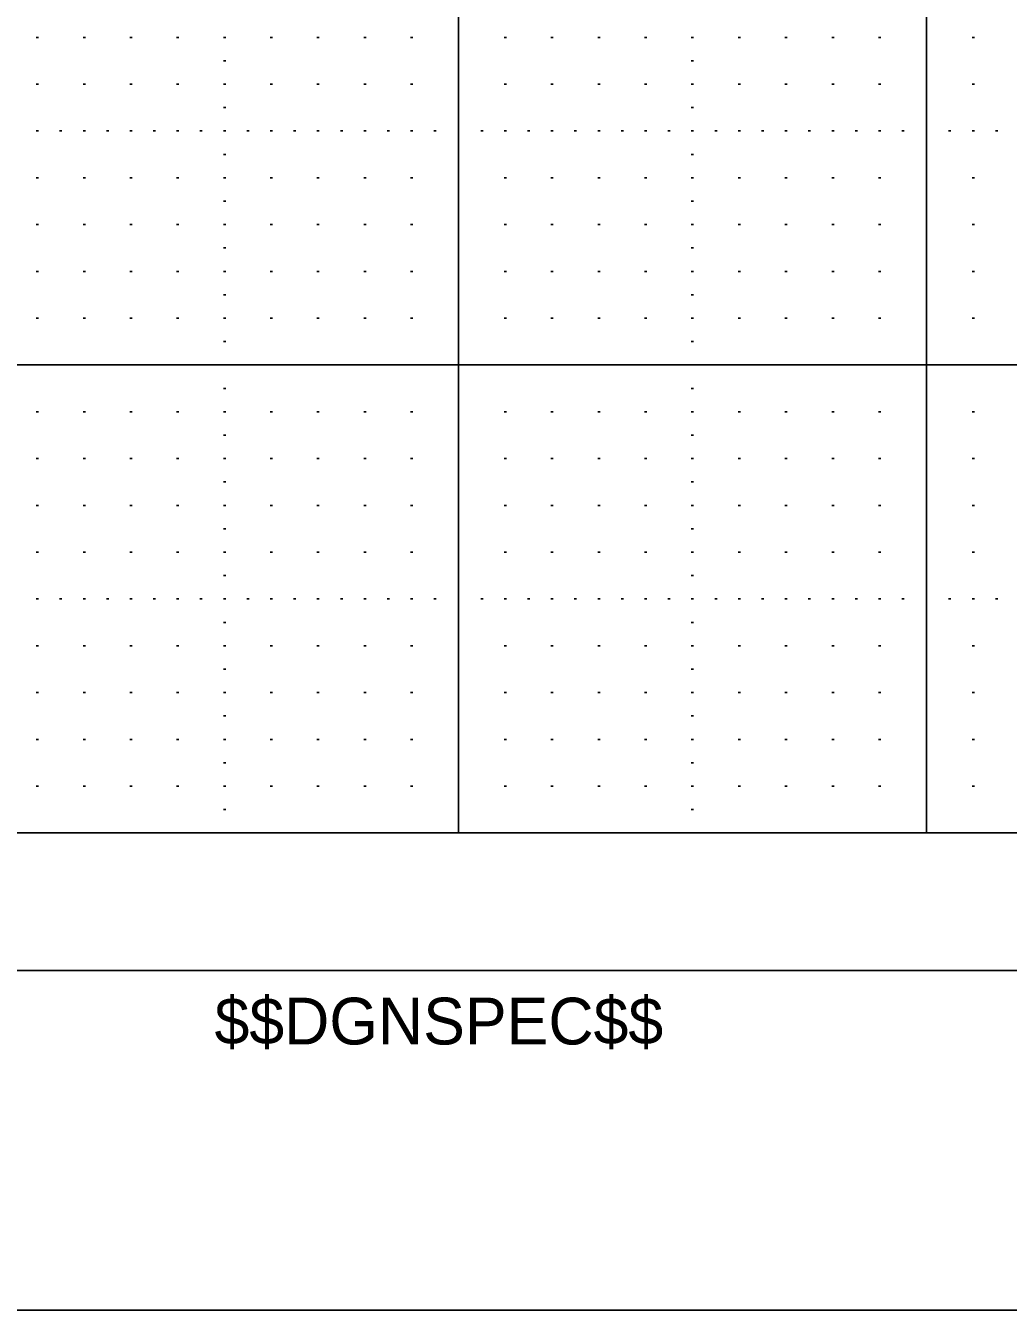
# Model space of a CAD drawing. Extents: x -1.6 to 32.4, y -0.7 to 21.3.
# Drawn here: x 21.82 to 23.92, y -0.727 to 2.018 of the extents above; entities that cross this region are included whole.
import ezdxf

# ---------------------------------------------------------------- set-up
doc = ezdxf.new("R2010")
doc.units = 0
for name, color, linetype in [('Level 1', 7, 'Continuous'), ('Level 4', 7, 'Continuous'), ('Level 48', 7, 'Continuous'), ('Level 5', 7, 'Continuous'), ('Level 63', 7, 'Continuous'), ('R_Border_Dark', 7, 'Continuous')]:
    doc.layers.add(name, color=color, linetype=linetype)

msp = doc.modelspace()

# ---------------------------------------------------------------- linework, layer by layer
at = {"layer": 'Level 1'}
msp.add_line((31.617, -0.001), (-0.001, -0.001), dxfattribs=at)
at = {"layer": 'Level 4'}
msp.add_line((31.617, 0.293), (-0.001, 0.293), dxfattribs=at)
at = {"layer": 'Level 5'}
for p, q in [((21.8425, 1.993), (21.8475, 1.993)), ((21.9425, 1.993), (21.9475, 1.993)), ((22.0425, 1.993), (22.0475, 1.993)), ((22.1425, 1.993), (22.1475, 1.993)), ((22.2425, 1.993), (22.2475, 1.993)), ((22.3425, 1.993), (22.3475, 1.993)), ((22.4425, 1.993), (22.4475, 1.993)), ((22.5425, 1.993), (22.5475, 1.993)), ((22.6425, 1.993), (22.6475, 1.993)), ((22.8425, 1.993), (22.8475, 1.993)), ((22.9425, 1.993), (22.9475, 1.993)), ((23.0425, 1.993), (23.0475, 1.993)), ((23.1425, 1.993), (23.1475, 1.993)), ((23.2425, 1.993), (23.2475, 1.993)), ((23.3425, 1.993), (23.3475, 1.993)), ((23.4425, 1.993), (23.4475, 1.993)), ((23.5425, 1.993), (23.5475, 1.993)), ((23.6425, 1.993), (23.6475, 1.993)), ((23.8425, 1.993), (23.8475, 1.993)), ((22.2425, 1.943), (22.2475, 1.943)), ((23.2425, 1.943), (23.2475, 1.943)), ((21.8425, 1.893), (21.8475, 1.893)), ((21.9425, 1.893), (21.9475, 1.893)), ((22.0425, 1.893), (22.0475, 1.893)), ((22.1425, 1.893), (22.1475, 1.893)), ((22.2425, 1.893), (22.2475, 1.893)), ((22.3425, 1.893), (22.3475, 1.893)), ((22.4425, 1.893), (22.4475, 1.893)), ((22.5425, 1.893), (22.5475, 1.893)), ((22.6425, 1.893), (22.6475, 1.893)), ((22.8425, 1.893), (22.8475, 1.893)), ((22.9425, 1.893), (22.9475, 1.893)), ((23.0425, 1.893), (23.0475, 1.893)), ((23.1425, 1.893), (23.1475, 1.893)), ((23.2425, 1.893), (23.2475, 1.893)), ((23.3425, 1.893), (23.3475, 1.893)), ((23.4425, 1.893), (23.4475, 1.893)), ((23.5425, 1.893), (23.5475, 1.893)), ((23.6425, 1.893), (23.6475, 1.893)), ((23.8425, 1.893), (23.8475, 1.893)), ((22.2425, 1.843), (22.2475, 1.843)), ((23.2425, 1.843), (23.2475, 1.843)), ((21.8425, 1.793), (21.8475, 1.793)), ((21.8925, 1.793), (21.8975, 1.793)), ((21.9425, 1.793), (21.9475, 1.793)), ((21.9925, 1.793), (21.9975, 1.793)), ((22.0425, 1.793), (22.0475, 1.793)), ((22.0925, 1.793), (22.0975, 1.793)), ((22.1425, 1.793), (22.1475, 1.793)), ((22.1925, 1.793), (22.1975, 1.793)), ((22.2425, 1.793), (22.2475, 1.793)), ((22.2925, 1.793), (22.2975, 1.793)), ((22.3425, 1.793), (22.3475, 1.793)), ((22.3925, 1.793), (22.3975, 1.793)), ((22.4425, 1.793), (22.4475, 1.793)), ((22.4925, 1.793), (22.4975, 1.793)), ((22.5425, 1.793), (22.5475, 1.793)), ((22.5925, 1.793), (22.5975, 1.793)), ((22.6425, 1.793), (22.6475, 1.793)), ((22.6925, 1.793), (22.6975, 1.793)), ((22.7925, 1.793), (22.7975, 1.793)), ((22.8425, 1.793), (22.8475, 1.793)), ((22.8925, 1.793), (22.8975, 1.793)), ((22.9425, 1.793), (22.9475, 1.793)), ((22.9925, 1.793), (22.9975, 1.793)), ((23.0425, 1.793), (23.0475, 1.793)), ((23.0925, 1.793), (23.0975, 1.793)), ((23.1425, 1.793), (23.1475, 1.793)), ((23.1925, 1.793), (23.1975, 1.793)), ((23.2425, 1.793), (23.2475, 1.793)), ((23.2925, 1.793), (23.2975, 1.793)), ((23.3425, 1.793), (23.3475, 1.793)), ((23.3925, 1.793), (23.3975, 1.793)), ((23.4425, 1.793), (23.4475, 1.793)), ((23.4925, 1.793), (23.4975, 1.793)), ((23.5425, 1.793), (23.5475, 1.793)), ((23.5925, 1.793), (23.5975, 1.793)), ((23.6425, 1.793), (23.6475, 1.793)), ((23.6925, 1.793), (23.6975, 1.793)), ((23.7925, 1.793), (23.7975, 1.793)), ((23.8425, 1.793), (23.8475, 1.793)), ((23.8925, 1.793), (23.8975, 1.793)), ((22.2425, 1.743), (22.2475, 1.743)), ((23.2425, 1.743), (23.2475, 1.743)), ((21.8425, 1.693), (21.8475, 1.693)), ((21.9425, 1.693), (21.9475, 1.693)), ((22.0425, 1.693), (22.0475, 1.693)), ((22.1425, 1.693), (22.1475, 1.693)), ((22.2425, 1.693), (22.2475, 1.693)), ((22.3425, 1.693), (22.3475, 1.693)), ((22.4425, 1.693), (22.4475, 1.693)), ((22.5425, 1.693), (22.5475, 1.693)), ((22.6425, 1.693), (22.6475, 1.693)), ((22.8425, 1.693), (22.8475, 1.693)), ((22.9425, 1.693), (22.9475, 1.693)), ((23.0425, 1.693), (23.0475, 1.693)), ((23.1425, 1.693), (23.1475, 1.693)), ((23.2425, 1.693), (23.2475, 1.693)), ((23.3425, 1.693), (23.3475, 1.693)), ((23.4425, 1.693), (23.4475, 1.693)), ((23.5425, 1.693), (23.5475, 1.693)), ((23.6425, 1.693), (23.6475, 1.693)), ((23.8425, 1.693), (23.8475, 1.693)), ((22.2425, 1.643), (22.2475, 1.643)), ((23.2425, 1.643), (23.2475, 1.643)), ((21.8425, 1.593), (21.8475, 1.593)), ((21.9425, 1.593), (21.9475, 1.593)), ((22.0425, 1.593), (22.0475, 1.593)), ((22.1425, 1.593), (22.1475, 1.593)), ((22.2425, 1.593), (22.2475, 1.593)), ((22.3425, 1.593), (22.3475, 1.593)), ((22.4425, 1.593), (22.4475, 1.593)), ((22.5425, 1.593), (22.5475, 1.593)), ((22.6425, 1.593), (22.6475, 1.593)), ((22.8425, 1.593), (22.8475, 1.593)), ((22.9425, 1.593), (22.9475, 1.593)), ((23.0425, 1.593), (23.0475, 1.593)), ((23.1425, 1.593), (23.1475, 1.593)), ((23.2425, 1.593), (23.2475, 1.593)), ((23.3425, 1.593), (23.3475, 1.593)), ((23.4425, 1.593), (23.4475, 1.593)), ((23.5425, 1.593), (23.5475, 1.593)), ((23.6425, 1.593), (23.6475, 1.593)), ((23.8425, 1.593), (23.8475, 1.593)), ((22.2425, 1.543), (22.2475, 1.543)), ((23.2425, 1.543), (23.2475, 1.543)), ((21.8425, 1.493), (21.8475, 1.493)), ((21.9425, 1.493), (21.9475, 1.493)), ((22.0425, 1.493), (22.0475, 1.493)), ((22.1425, 1.493), (22.1475, 1.493)), ((22.2425, 1.493), (22.2475, 1.493)), ((22.3425, 1.493), (22.3475, 1.493)), ((22.4425, 1.493), (22.4475, 1.493)), ((22.5425, 1.493), (22.5475, 1.493)), ((22.6425, 1.493), (22.6475, 1.493)), ((22.8425, 1.493), (22.8475, 1.493)), ((22.9425, 1.493), (22.9475, 1.493)), ((23.0425, 1.493), (23.0475, 1.493)), ((23.1425, 1.493), (23.1475, 1.493)), ((23.2425, 1.493), (23.2475, 1.493)), ((23.3425, 1.493), (23.3475, 1.493)), ((23.4425, 1.493), (23.4475, 1.493)), ((23.5425, 1.493), (23.5475, 1.493)), ((23.6425, 1.493), (23.6475, 1.493)), ((23.8425, 1.493), (23.8475, 1.493)), ((22.2425, 1.443), (22.2475, 1.443)), ((23.2425, 1.443), (23.2475, 1.443)), ((21.8425, 1.393), (21.8475, 1.393)), ((21.9425, 1.393), (21.9475, 1.393)), ((22.0425, 1.393), (22.0475, 1.393)), ((22.1425, 1.393), (22.1475, 1.393)), ((22.2425, 1.393), (22.2475, 1.393)), ((22.3425, 1.393), (22.3475, 1.393)), ((22.4425, 1.393), (22.4475, 1.393)), ((22.5425, 1.393), (22.5475, 1.393)), ((22.6425, 1.393), (22.6475, 1.393)), ((22.8425, 1.393), (22.8475, 1.393)), ((22.9425, 1.393), (22.9475, 1.393)), ((23.0425, 1.393), (23.0475, 1.393)), ((23.1425, 1.393), (23.1475, 1.393)), ((23.2425, 1.393), (23.2475, 1.393)), ((23.3425, 1.393), (23.3475, 1.393)), ((23.4425, 1.393), (23.4475, 1.393)), ((23.5425, 1.393), (23.5475, 1.393)), ((23.6425, 1.393), (23.6475, 1.393)), ((23.8425, 1.393), (23.8475, 1.393)), ((22.2425, 1.343), (22.2475, 1.343)), ((23.2425, 1.343), (23.2475, 1.343)), ((22.2425, 1.243), (22.2475, 1.243)), ((23.2425, 1.243), (23.2475, 1.243)), ((21.8425, 1.193), (21.8475, 1.193)), ((21.9425, 1.193), (21.9475, 1.193)), ((22.0425, 1.193), (22.0475, 1.193)), ((22.1425, 1.193), (22.1475, 1.193)), ((22.2425, 1.193), (22.2475, 1.193)), ((22.3425, 1.193), (22.3475, 1.193)), ((22.4425, 1.193), (22.4475, 1.193)), ((22.5425, 1.193), (22.5475, 1.193)), ((22.6425, 1.193), (22.6475, 1.193)), ((22.8425, 1.193), (22.8475, 1.193)), ((22.9425, 1.193), (22.9475, 1.193)), ((23.0425, 1.193), (23.0475, 1.193)), ((23.1425, 1.193), (23.1475, 1.193)), ((23.2425, 1.193), (23.2475, 1.193)), ((23.3425, 1.193), (23.3475, 1.193)), ((23.4425, 1.193), (23.4475, 1.193)), ((23.5425, 1.193), (23.5475, 1.193)), ((23.6425, 1.193), (23.6475, 1.193)), ((23.8425, 1.193), (23.8475, 1.193)), ((22.2425, 1.143), (22.2475, 1.143)), ((23.2425, 1.143), (23.2475, 1.143)), ((21.8425, 1.093), (21.8475, 1.093)), ((21.9425, 1.093), (21.9475, 1.093)), ((22.0425, 1.093), (22.0475, 1.093)), ((22.1425, 1.093), (22.1475, 1.093)), ((22.2425, 1.093), (22.2475, 1.093)), ((22.3425, 1.093), (22.3475, 1.093)), ((22.4425, 1.093), (22.4475, 1.093)), ((22.5425, 1.093), (22.5475, 1.093)), ((22.6425, 1.093), (22.6475, 1.093)), ((22.8425, 1.093), (22.8475, 1.093)), ((22.9425, 1.093), (22.9475, 1.093)), ((23.0425, 1.093), (23.0475, 1.093)), ((23.1425, 1.093), (23.1475, 1.093)), ((23.2425, 1.093), (23.2475, 1.093)), ((23.3425, 1.093), (23.3475, 1.093)), ((23.4425, 1.093), (23.4475, 1.093)), ((23.5425, 1.093), (23.5475, 1.093)), ((23.6425, 1.093), (23.6475, 1.093)), ((23.8425, 1.093), (23.8475, 1.093)), ((22.2425, 1.043), (22.2475, 1.043)), ((23.2425, 1.043), (23.2475, 1.043)), ((21.8425, 0.993), (21.8475, 0.993)), ((21.9425, 0.993), (21.9475, 0.993)), ((22.0425, 0.993), (22.0475, 0.993)), ((22.1425, 0.993), (22.1475, 0.993)), ((22.2425, 0.993), (22.2475, 0.993)), ((22.3425, 0.993), (22.3475, 0.993)), ((22.4425, 0.993), (22.4475, 0.993)), ((22.5425, 0.993), (22.5475, 0.993)), ((22.6425, 0.993), (22.6475, 0.993)), ((22.8425, 0.993), (22.8475, 0.993)), ((22.9425, 0.993), (22.9475, 0.993)), ((23.0425, 0.993), (23.0475, 0.993)), ((23.1425, 0.993), (23.1475, 0.993)), ((23.2425, 0.993), (23.2475, 0.993)), ((23.3425, 0.993), (23.3475, 0.993)), ((23.4425, 0.993), (23.4475, 0.993)), ((23.5425, 0.993), (23.5475, 0.993)), ((23.6425, 0.993), (23.6475, 0.993)), ((23.8425, 0.993), (23.8475, 0.993)), ((22.2425, 0.943), (22.2475, 0.943)), ((23.2425, 0.943), (23.2475, 0.943)), ((21.8425, 0.893), (21.8475, 0.893)), ((21.9425, 0.893), (21.9475, 0.893)), ((22.0425, 0.893), (22.0475, 0.893)), ((22.1425, 0.893), (22.1475, 0.893)), ((22.2425, 0.893), (22.2475, 0.893)), ((22.3425, 0.893), (22.3475, 0.893)), ((22.4425, 0.893), (22.4475, 0.893)), ((22.5425, 0.893), (22.5475, 0.893)), ((22.6425, 0.893), (22.6475, 0.893)), ((22.8425, 0.893), (22.8475, 0.893)), ((22.9425, 0.893), (22.9475, 0.893)), ((23.0425, 0.893), (23.0475, 0.893)), ((23.1425, 0.893), (23.1475, 0.893)), ((23.2425, 0.893), (23.2475, 0.893)), ((23.3425, 0.893), (23.3475, 0.893)), ((23.4425, 0.893), (23.4475, 0.893)), ((23.5425, 0.893), (23.5475, 0.893)), ((23.6425, 0.893), (23.6475, 0.893)), ((23.8425, 0.893), (23.8475, 0.893)), ((22.2425, 0.843), (22.2475, 0.843)), ((23.2425, 0.843), (23.2475, 0.843)), ((21.8425, 0.793), (21.8475, 0.793)), ((21.8925, 0.793), (21.8975, 0.793)), ((21.9425, 0.793), (21.9475, 0.793)), ((21.9925, 0.793), (21.9975, 0.793)), ((22.0425, 0.793), (22.0475, 0.793)), ((22.0925, 0.793), (22.0975, 0.793)), ((22.1425, 0.793), (22.1475, 0.793)), ((22.1925, 0.793), (22.1975, 0.793)), ((22.2425, 0.793), (22.2475, 0.793)), ((22.2925, 0.793), (22.2975, 0.793)), ((22.3425, 0.793), (22.3475, 0.793)), ((22.3925, 0.793), (22.3975, 0.793)), ((22.4425, 0.793), (22.4475, 0.793)), ((22.4925, 0.793), (22.4975, 0.793)), ((22.5425, 0.793), (22.5475, 0.793)), ((22.5925, 0.793), (22.5975, 0.793)), ((22.6425, 0.793), (22.6475, 0.793)), ((22.6925, 0.793), (22.6975, 0.793)), ((22.7925, 0.793), (22.7975, 0.793)), ((22.8425, 0.793), (22.8475, 0.793)), ((22.8925, 0.793), (22.8975, 0.793)), ((22.9425, 0.793), (22.9475, 0.793)), ((22.9925, 0.793), (22.9975, 0.793)), ((23.0425, 0.793), (23.0475, 0.793)), ((23.0925, 0.793), (23.0975, 0.793)), ((23.1425, 0.793), (23.1475, 0.793)), ((23.1925, 0.793), (23.1975, 0.793)), ((23.2425, 0.793), (23.2475, 0.793)), ((23.2925, 0.793), (23.2975, 0.793)), ((23.3425, 0.793), (23.3475, 0.793)), ((23.3925, 0.793), (23.3975, 0.793)), ((23.4425, 0.793), (23.4475, 0.793)), ((23.4925, 0.793), (23.4975, 0.793)), ((23.5425, 0.793), (23.5475, 0.793)), ((23.5925, 0.793), (23.5975, 0.793)), ((23.6425, 0.793), (23.6475, 0.793)), ((23.6925, 0.793), (23.6975, 0.793)), ((23.7925, 0.793), (23.7975, 0.793)), ((23.8425, 0.793), (23.8475, 0.793)), ((23.8925, 0.793), (23.8975, 0.793)), ((22.2425, 0.743), (22.2475, 0.743)), ((23.2425, 0.743), (23.2475, 0.743)), ((21.8425, 0.693), (21.8475, 0.693)), ((21.9425, 0.693), (21.9475, 0.693)), ((22.0425, 0.693), (22.0475, 0.693)), ((22.1425, 0.693), (22.1475, 0.693)), ((22.2425, 0.693), (22.2475, 0.693)), ((22.3425, 0.693), (22.3475, 0.693)), ((22.4425, 0.693), (22.4475, 0.693)), ((22.5425, 0.693), (22.5475, 0.693)), ((22.6425, 0.693), (22.6475, 0.693)), ((22.8425, 0.693), (22.8475, 0.693)), ((22.9425, 0.693), (22.9475, 0.693)), ((23.0425, 0.693), (23.0475, 0.693)), ((23.1425, 0.693), (23.1475, 0.693)), ((23.2425, 0.693), (23.2475, 0.693)), ((23.3425, 0.693), (23.3475, 0.693)), ((23.4425, 0.693), (23.4475, 0.693)), ((23.5425, 0.693), (23.5475, 0.693)), ((23.6425, 0.693), (23.6475, 0.693)), ((23.8425, 0.693), (23.8475, 0.693)), ((22.2425, 0.643), (22.2475, 0.643)), ((23.2425, 0.643), (23.2475, 0.643)), ((21.8425, 0.593), (21.8475, 0.593)), ((21.9425, 0.593), (21.9475, 0.593)), ((22.0425, 0.593), (22.0475, 0.593)), ((22.1425, 0.593), (22.1475, 0.593)), ((22.2425, 0.593), (22.2475, 0.593)), ((22.3425, 0.593), (22.3475, 0.593)), ((22.4425, 0.593), (22.4475, 0.593)), ((22.5425, 0.593), (22.5475, 0.593)), ((22.6425, 0.593), (22.6475, 0.593)), ((22.8425, 0.593), (22.8475, 0.593)), ((22.9425, 0.593), (22.9475, 0.593)), ((23.0425, 0.593), (23.0475, 0.593)), ((23.1425, 0.593), (23.1475, 0.593)), ((23.2425, 0.593), (23.2475, 0.593)), ((23.3425, 0.593), (23.3475, 0.593)), ((23.4425, 0.593), (23.4475, 0.593)), ((23.5425, 0.593), (23.5475, 0.593)), ((23.6425, 0.593), (23.6475, 0.593)), ((23.8425, 0.593), (23.8475, 0.593)), ((22.2425, 0.543), (22.2475, 0.543)), ((23.2425, 0.543), (23.2475, 0.543)), ((21.8425, 0.493), (21.8475, 0.493)), ((21.9425, 0.493), (21.9475, 0.493)), ((22.0425, 0.493), (22.0475, 0.493)), ((22.1425, 0.493), (22.1475, 0.493)), ((22.2425, 0.493), (22.2475, 0.493)), ((22.3425, 0.493), (22.3475, 0.493)), ((22.4425, 0.493), (22.4475, 0.493)), ((22.5425, 0.493), (22.5475, 0.493)), ((22.6425, 0.493), (22.6475, 0.493)), ((22.8425, 0.493), (22.8475, 0.493)), ((22.9425, 0.493), (22.9475, 0.493)), ((23.0425, 0.493), (23.0475, 0.493)), ((23.1425, 0.493), (23.1475, 0.493)), ((23.2425, 0.493), (23.2475, 0.493)), ((23.3425, 0.493), (23.3475, 0.493)), ((23.4425, 0.493), (23.4475, 0.493)), ((23.5425, 0.493), (23.5475, 0.493)), ((23.6425, 0.493), (23.6475, 0.493)), ((23.8425, 0.493), (23.8475, 0.493)), ((22.2425, 0.443), (22.2475, 0.443)), ((23.2425, 0.443), (23.2475, 0.443)), ((21.8425, 0.393), (21.8475, 0.393)), ((21.9425, 0.393), (21.9475, 0.393)), ((22.0425, 0.393), (22.0475, 0.393)), ((22.1425, 0.393), (22.1475, 0.393)), ((22.2425, 0.393), (22.2475, 0.393)), ((22.3425, 0.393), (22.3475, 0.393)), ((22.4425, 0.393), (22.4475, 0.393)), ((22.5425, 0.393), (22.5475, 0.393)), ((22.6425, 0.393), (22.6475, 0.393)), ((22.8425, 0.393), (22.8475, 0.393)), ((22.9425, 0.393), (22.9475, 0.393)), ((23.0425, 0.393), (23.0475, 0.393)), ((23.1425, 0.393), (23.1475, 0.393)), ((23.2425, 0.393), (23.2475, 0.393)), ((23.3425, 0.393), (23.3475, 0.393)), ((23.4425, 0.393), (23.4475, 0.393)), ((23.5425, 0.393), (23.5475, 0.393)), ((23.6425, 0.393), (23.6475, 0.393)), ((23.8425, 0.393), (23.8475, 0.393)), ((22.2425, 0.343), (22.2475, 0.343)), ((23.2425, 0.343), (23.2475, 0.343))]:
    msp.add_line(p, q, dxfattribs=at)
at = {"layer": 'Level 63'}
msp.add_lwpolyline([(-1.598, -0.727), (32.402, -0.727), (32.402, 21.273), (-1.598, 21.273)], close=True, dxfattribs=at)
msp.add_lwpolyline([(30.745, 8.293), (30.745, 0.293), (0.745, 0.293), (0.745, 8.293)], dxfattribs=at)
at = {"layer": 'R_Border_Dark'}
for p, q in [((22.745, 0.293), (22.745, 8.293)), ((23.745, 0.293), (23.745, 8.293)), ((31.617, 1.293), (-0.001, 1.293))]:
    msp.add_line(p, q, dxfattribs=at)
msp.add_lwpolyline([(30.745, 8.293), (30.745, 0.293), (0.745, 0.293), (0.745, 8.293)], dxfattribs=at)

# ---------------------------------------------------------------- texts
at = {"layer": 'Level 48'}
msp.add_text('$$DGNSPEC$$', height=0.100002, dxfattribs=at).set_placement((22.2236, -0.159))

doc.saveas('drawing.dxf')
